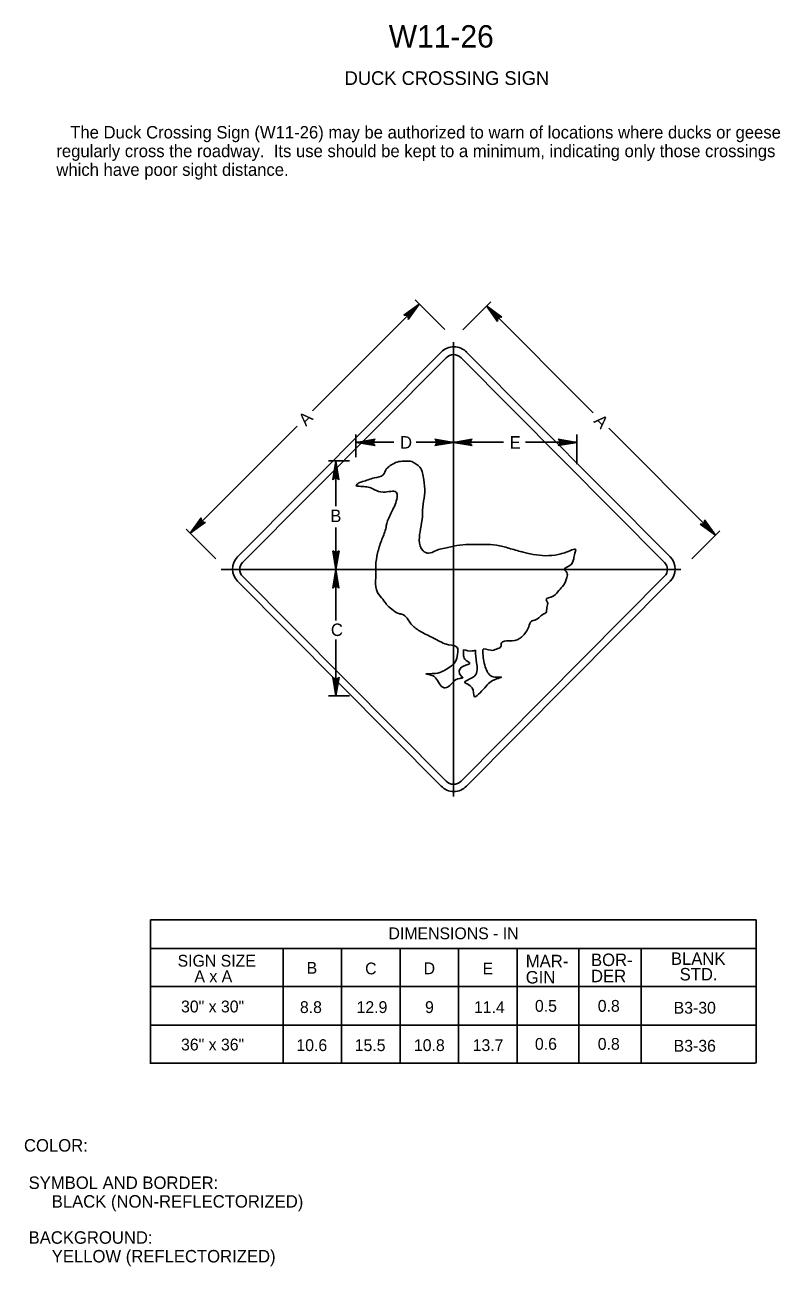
# Model space of a CAD drawing. Extents: x -0.108 to 0.178, y 0.004 to 0.272.
# Drawn here: x 0.0262 to 0.1778, y 0.0099 to 0.2591 of the extents above; entities that cross this region are included whole.
import ezdxf

# ---------------------------------------------------------------- set-up
doc = ezdxf.new("R2010")
doc.units = 0
for name, color, linetype in [('1', 7, 'Continuous'), ('2', 7, 'Continuous'), ('3', 7, 'Continuous')]:
    doc.layers.add(name, color=color, linetype=linetype)

# ---------------------------------------------------------------- blocks, each defined once
blk = doc.blocks.new('RARROW')
at = {"layer": '3'}
for p, q in [((-2.156, 0.28500000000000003), (-2.2665, 0.384625)), ((-2.2665, 0.384625), (0, 0)), ((0, 0), (-2.2665, -0.379125)), ((-2.156, 0.28500000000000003), (-2.075625, 0.12075)), ((0, 0), (-2.156, 0.28500000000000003)), ((-2.14975, -0.2705), (0, 0)), ((-2.075625, 0.12075), (0, 0)), ((0, 0), (-2.074, -0.108)), ((-2.2665, -0.379125), (-2.14975, -0.2705)), ((-2.074, -0.108), (-2.14975, -0.2705))]:
    blk.add_line(p, q, dxfattribs=at)

msp = doc.modelspace()

# ---------------------------------------------------------------- linework, layer by layer
at = {"layer": '3'}
for p, q in [((0.08394695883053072, 0.1815719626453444), (0.105375, 0.203)), ((0.11049991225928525, 0.19787508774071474), (0.10453356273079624, 0.20384143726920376)), ((0.11411698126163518, 0.19786698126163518), (0.11973788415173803, 0.20348788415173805)), ((0.1403030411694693, 0.1811969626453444), (0.11887500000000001, 0.202625)), ((0.11225, 0.195375), (0.11225, 0.104125)), ((0.068875, 0.15225), (0.10975, 0.193375)), ((0.069875, 0.151125), (0.11075, 0.19225)), ((0.11375, 0.19225), (0.154625, 0.151125)), ((0.114875, 0.193375), (0.15575, 0.15225)), ((0.08085336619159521, 0.17847837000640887), (0.059375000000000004, 0.157)), ((0.11224962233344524, 0.17144555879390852), (0.11224962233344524, 0.1773597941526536)), ((0.14339662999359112, 0.17810337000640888), (0.164875, 0.15662500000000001)), ((0.09260896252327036, 0.17228588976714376), (0.09260896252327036, 0.1768178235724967)), ((0.09275, 0.1752892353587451), (0.10025, 0.1752892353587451)), ((0.10475, 0.1752892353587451), (0.11225, 0.1752892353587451)), ((0.11225, 0.1752892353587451), (0.12225846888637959, 0.1752892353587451)), ((0.1267205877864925, 0.1752892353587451), (0.137, 0.1752892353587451)), ((0.13701126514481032, 0.17090358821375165), (0.13701126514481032, 0.1768178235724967)), ((0.11225, 0.1737892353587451), (0.11225, 0.1740392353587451)), ((0.09137756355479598, 0.17154653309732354), (0.08716625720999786, 0.17154653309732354)), ((0.08862756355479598, 0.17154379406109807), (0.08862756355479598, 0.16244768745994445)), ((0.06449991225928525, 0.15187508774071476), (0.058533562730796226, 0.15784143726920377)), ((0.08862756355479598, 0.1581581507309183), (0.08862756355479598, 0.14975)), ((0.16011698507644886, 0.15186698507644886), (0.16573788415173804, 0.15748788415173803)), ((0.065625, 0.14975), (0.15787500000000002, 0.14975)), ((0.09137756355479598, 0.14974726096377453), (0.08716625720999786, 0.14974726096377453)), ((0.08862756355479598, 0.1395092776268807), (0.08862756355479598, 0.14975)), ((0.10975, 0.10625), (0.068875, 0.147375)), ((0.11075, 0.10725), (0.069875, 0.148375)), ((0.154625, 0.148375), (0.11375, 0.10725)), ((0.15575, 0.147375), (0.114875, 0.10625)), ((0.08862756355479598, 0.12441879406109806), (0.08862756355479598, 0.1356472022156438)), ((0.09137756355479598, 0.12437864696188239), (0.08716625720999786, 0.12437864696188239)), ((0.051375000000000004, 0.079375), (0.17300000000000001, 0.079375)), ((0.051375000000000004, 0.079375), (0.051375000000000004, 0.050616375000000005)), ((0.17300000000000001, 0.079375), (0.17300000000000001, 0.050616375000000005)), ((0.17300000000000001, 0.073625), (0.051375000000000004, 0.073625)), ((0.07803934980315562, 0.07358609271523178), (0.07803934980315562, 0.050616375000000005)), ((0.08975, 0.073625), (0.08975, 0.050616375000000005)), ((0.1015, 0.073625), (0.1015, 0.050616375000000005)), ((0.11325, 0.073625), (0.11325, 0.050616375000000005)), ((0.12499776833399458, 0.07358896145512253), (0.12499776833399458, 0.050616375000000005)), ((0.1374312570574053, 0.07358896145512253), (0.1374312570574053, 0.050616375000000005)), ((0.1499126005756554, 0.07358896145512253), (0.1499126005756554, 0.050616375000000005)), ((0.051375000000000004, 0.066), (0.17300000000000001, 0.066)), ((0.051375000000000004, 0.05825), (0.17300000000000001, 0.05825)), ((0.05128208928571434, 0.050616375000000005), (0.17290708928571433, 0.050616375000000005))]:
    msp.add_line(p, q, dxfattribs=at)
for centre, radius, start, end in [((0.11231283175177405, 0.19081283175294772), 0.0036239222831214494, 44.07799722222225, 135.0074166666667), ((0.11225000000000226, 0.19077413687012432), 0.002104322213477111, 44.535288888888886, 135.46470833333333), ((0.07134537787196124, 0.1498124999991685), 0.003470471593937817, 135.38381944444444, 224.61618333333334), ((0.15326897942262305, 0.14981249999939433), 0.0034780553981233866, 315.50695833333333, 44.49304444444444), ((0.0712685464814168, 0.14975000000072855), 0.0019577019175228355, 135.38381666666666, 224.61618055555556), ((0.153225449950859, 0.14974999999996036), 0.0019619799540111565, 315.50695833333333, 44.49304444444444), ((0.11224999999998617, 0.10868497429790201), 0.00207584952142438, 223.73079444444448, 316.2692083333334), ((0.11231249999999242, 0.1087014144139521), 0.003546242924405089, 223.73079444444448, 316.2692083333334)]:
    msp.add_arc(centre, radius, start, end, dxfattribs=at)
for points in [[(0.11812500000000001, 0.133375), (0.11812500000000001, 0.133625), (0.11975000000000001, 0.1335), (0.120875, 0.13375), (0.12175, 0.13425), (0.121875, 0.135), (0.123375, 0.135375), (0.1255, 0.135875), (0.126, 0.13625), (0.12675, 0.137125), (0.12737500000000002, 0.13825), (0.12787500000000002, 0.139375), (0.12825, 0.1395), (0.129375, 0.14), (0.13025, 0.14075000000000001), (0.13075, 0.14100000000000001), (0.131, 0.142125), (0.131125, 0.143125), (0.130875, 0.143625), (0.13225, 0.144375), (0.133375, 0.1455), (0.134375, 0.146625), (0.135, 0.148125), (0.135, 0.149125), (0.1345, 0.14975), (0.135625, 0.1505), (0.136375, 0.151875), (0.136625, 0.153), (0.13675, 0.15375), (0.135625, 0.1535), (0.13425, 0.153), (0.13325, 0.15275), (0.13075, 0.1525), (0.12825, 0.15275), (0.127, 0.153), (0.126, 0.15325), (0.123375, 0.154), (0.120875, 0.154625), (0.11850000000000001, 0.15475), (0.116, 0.15475), (0.1135, 0.154625), (0.111125, 0.154125), (0.108625, 0.1535), (0.10725, 0.153), (0.106125, 0.1535), (0.105375, 0.155625), (0.105625, 0.15787500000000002), (0.106, 0.160375), (0.106125, 0.162875), (0.1065, 0.16525), (0.10625, 0.16775), (0.1055, 0.17025), (0.10475, 0.170875), (0.10387500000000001, 0.171375), (0.10262500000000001, 0.1715), (0.10125, 0.171375), (0.1, 0.170875), (0.099125, 0.17025), (0.09875, 0.169875), (0.098125, 0.16875), (0.096375, 0.168125), (0.095125, 0.16775), (0.094, 0.167375), (0.09325, 0.167125), (0.092625, 0.1665)], [(0.092625, 0.1665), (0.094, 0.166375), (0.095125, 0.16625), (0.096375, 0.16575), (0.098125, 0.16525), (0.10075, 0.16525), (0.1005, 0.16275), (0.099375, 0.160375), (0.09875, 0.1585), (0.098625, 0.15787500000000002), (0.09775, 0.1555), (0.097, 0.153), (0.096625, 0.1505), (0.096625, 0.148125), (0.09675, 0.145625), (0.0985, 0.143125), (0.09875, 0.14275000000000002), (0.099875, 0.14175000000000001), (0.10125, 0.140875), (0.10187500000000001, 0.14075000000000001), (0.10375000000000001, 0.13875), (0.10425, 0.13825), (0.106125, 0.137), (0.108625, 0.13575), (0.11125, 0.134625), (0.113125, 0.13375), (0.113125, 0.133625)], [(0.113125, 0.134), (0.112375, 0.130875), (0.11125, 0.13), (0.108625, 0.128875), (0.10675, 0.12875), (0.108125, 0.128375), (0.108625, 0.128), (0.110375, 0.126), (0.11125, 0.12625), (0.1135, 0.12787500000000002), (0.114125, 0.128), (0.11375, 0.128375), (0.113875, 0.130125), (0.1155, 0.130875), (0.1145, 0.13175), (0.11425, 0.132625), (0.11425, 0.133625)], [(0.11425, 0.133625), (0.116, 0.133375), (0.116625, 0.1335)], [(0.116625, 0.1335), (0.116875, 0.131), (0.117, 0.129625), (0.1165, 0.128375), (0.116, 0.128), (0.1145, 0.12712500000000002), (0.116, 0.126), (0.116375, 0.12425), (0.11850000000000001, 0.126), (0.120875, 0.12775), (0.121875, 0.128125), (0.120875, 0.128125), (0.11975000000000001, 0.128375), (0.11850000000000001, 0.1305), (0.11812500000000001, 0.133625)]]:
    msp.add_spline(points, degree=3, dxfattribs=at)

# ---------------------------------------------------------------- block references
for p, xscale, yscale, rotation in [((0.105375, 0.203), 0.001654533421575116, 0.001636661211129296, 45), ((0.11887500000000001, 0.202625), 0.0016545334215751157, 0.001636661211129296, 135), ((0.09275, 0.17525000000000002), 0.0016545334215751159, 0.0016366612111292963, 180), ((0.11225, 0.17525000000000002), 0.0016545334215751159, 0.0016366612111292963, 180), ((0.088625, 0.1715), 0.0016545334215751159, 0.0016366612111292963, 90), ((0.059375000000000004, 0.157), 0.001654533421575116, 0.0016366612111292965, -135.00000000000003), ((0.164875, 0.15662500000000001), 0.001654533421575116, 0.001636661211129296, -45), ((0.088625, 0.14975), 0.0016545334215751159, 0.0016366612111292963, -90), ((0.088625, 0.14975), 0.0016545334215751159, 0.0016366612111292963, 90), ((0.088625, 0.124375), 0.0016545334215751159, 0.0016366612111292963, -90)]:
    msp.add_blockref('RARROW', p, dxfattribs=dict(at, xscale=xscale, yscale=yscale, rotation=rotation))
at = {"layer": '3', "xscale": 0.0016545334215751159, "yscale": 0.0016366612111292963}
for p in [(0.11225, 0.17525000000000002), (0.137, 0.17525000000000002)]:
    msp.add_blockref('RARROW', p, dxfattribs=at)

# ---------------------------------------------------------------- texts
at = {"layer": '1'}
for s, height, p in [('W11-26', 0.0045000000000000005, (0.09925, 0.2545)), ('DUCK CROSSING SIGN', 0.00275025, (0.090375, 0.247)), ('D', 0.0024997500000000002, (0.1015, 0.17400000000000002)), ('E', 0.0024997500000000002, (0.1235, 0.17400000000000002)), ('COLOR:', 0.0024997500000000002, (0.026000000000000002, 0.032875)), (' SYMBOL AND BORDER:', 0.0024997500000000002, (0.026000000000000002, 0.025375)), ('      BLACK (NON-REFLECTORIZED)', 0.0024997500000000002, (0.026000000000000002, 0.021625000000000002)), (' BACKGROUND:', 0.0024997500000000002, (0.026000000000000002, 0.014375)), ('      YELLOW (REFLECTORIZED)', 0.0024997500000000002, (0.026000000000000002, 0.010625))]:
    msp.add_text(s, height=height, dxfattribs=at).set_placement(p)
at = {"layer": '2'}
for s, p in [('   The Duck Crossing Sign (W11-26) may be authorized to warn of locations where ducks or geese ', (0.0325, 0.23625000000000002)), ('regularly cross the roadway.  Its use should be kept to a minimum, indicating only those crossings ', (0.0325, 0.2325)), ('which have poor sight distance.', (0.0325, 0.22875))]:
    msp.add_text(s, height=0.0024997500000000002, dxfattribs=at).set_placement(p)
at = {"layer": '3'}
for rotation, p in [(45, (0.082625, 0.178375)), (315, (0.14025, 0.179375))]:
    msp.add_text('A', height=0.0024997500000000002, rotation=rotation, dxfattribs=at).set_placement(p)
for s, height, p in [('B', 0.0024997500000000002, (0.08750000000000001, 0.15925)), ('C', 0.0024997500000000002, (0.08762500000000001, 0.136375)), ('DIMENSIONS - IN', 0.0023752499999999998, (0.09919159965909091, 0.0755)), ('SIGN SIZE', 0.0023752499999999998, (0.05684753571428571, 0.07)), ('MAR-', 0.0024997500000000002, (0.12675, 0.069875)), ('BOR-', 0.0024997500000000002, (0.13984650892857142, 0.070125)), ('BLANK', 0.0024997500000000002, (0.15589375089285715, 0.07035983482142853)), ('B', 0.0023752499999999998, (0.08275, 0.0685731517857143)), ('C', 0.0023752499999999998, (0.0945, 0.06844866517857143)), ('D', 0.0023752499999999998, (0.10625, 0.0684735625)), ('E', 0.0023752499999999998, (0.11807674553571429, 0.06844866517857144)), ('A x A', 0.0023752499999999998, (0.060222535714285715, 0.066875)), ('GIN', 0.0024997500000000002, (0.12675, 0.066625)), ('DER', 0.0024997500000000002, (0.13984650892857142, 0.066875)), ('STD.', 0.0024997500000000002, (0.15764375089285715, 0.06723483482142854)), ('30" x 30"', 0.0023752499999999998, (0.05753491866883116, 0.060812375)), ('8.8', 0.0023752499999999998, (0.08140330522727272, 0.060687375)), ('12.9', 0.0023752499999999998, (0.09277733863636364, 0.060687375)), ('9', 0.0023752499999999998, (0.10652566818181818, 0.060687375)), ('11.4', 0.0023752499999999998, (0.11635315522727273, 0.060687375)), ('0.5', 0.0023752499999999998, (0.1285939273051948, 0.060937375)), ('0.8', 0.0023752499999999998, (0.14120257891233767, 0.060937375)), ('B3-30', 0.0023752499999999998, (0.1564388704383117, 0.060562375)), ('36" x 36"', 0.0023752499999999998, (0.05753491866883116, 0.05317875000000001)), ('10.6', 0.0023752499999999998, (0.08069648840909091, 0.05305375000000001)), ('15.5', 0.0023752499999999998, (0.09240983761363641, 0.05305375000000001)), ('10.8', 0.0023752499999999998, (0.10429287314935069, 0.05305375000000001)), ('13.7', 0.0023752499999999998, (0.1160914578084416, 0.05305375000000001)), ('0.6', 0.0023752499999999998, (0.1285910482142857, 0.05330375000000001)), ('0.8', 0.0023752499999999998, (0.14120257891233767, 0.05330375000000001)), ('B3-36', 0.0023752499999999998, (0.15644390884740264, 0.05292875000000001))]:
    msp.add_text(s, height=height, dxfattribs=at).set_placement(p)

doc.saveas('drawing.dxf')
